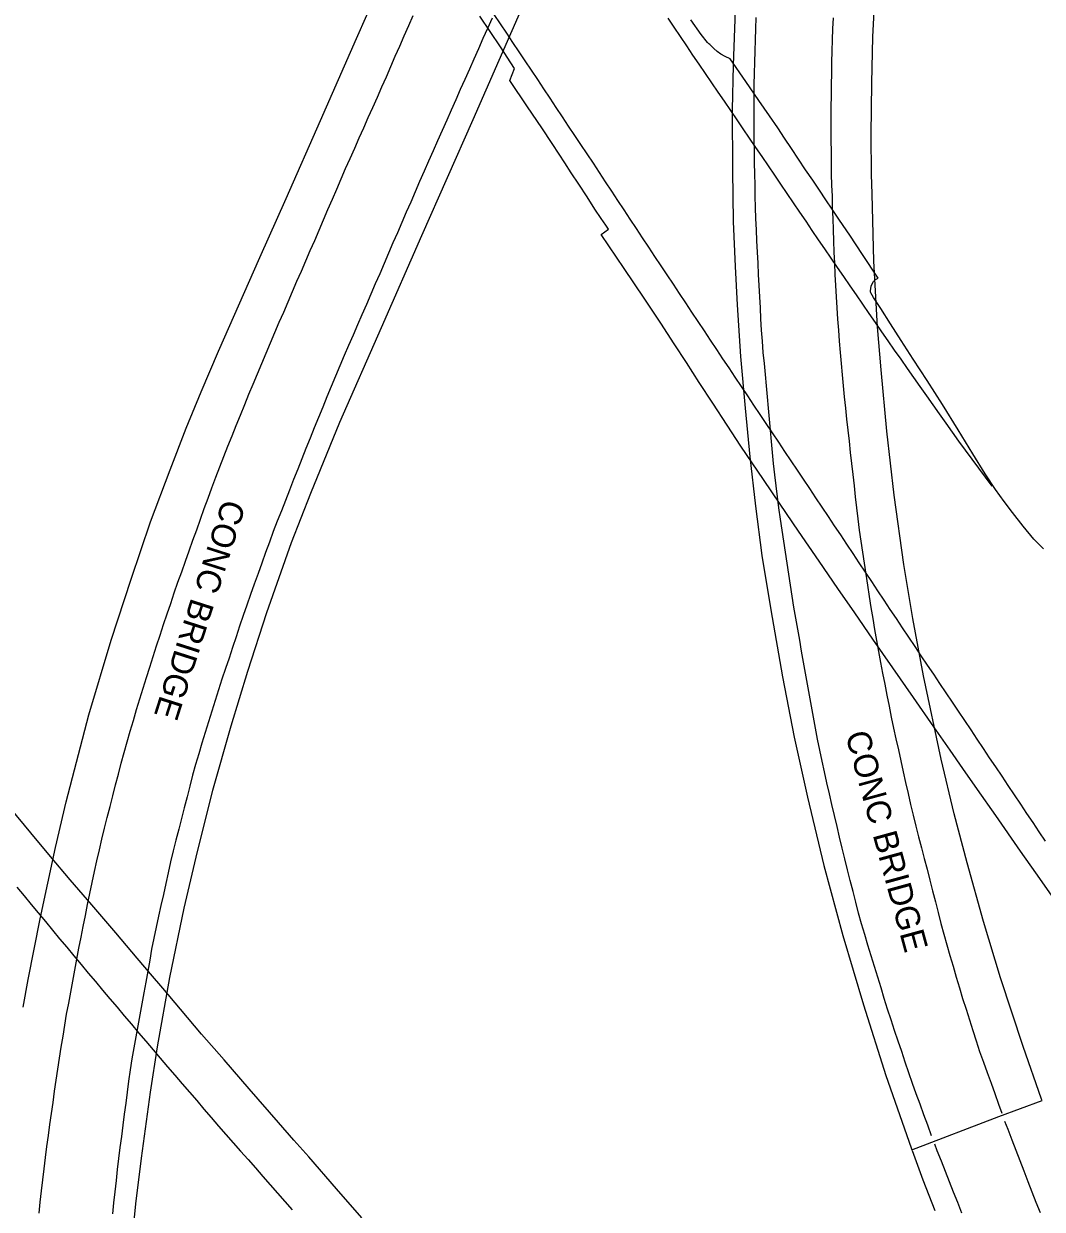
# Model space of a CAD drawing. Extents: x 1948091 to 1975253, y 787267 to 823306.
# Drawn here: x 1971410.9 to 1971639, y 795716.4 to 795981.8 of the extents above; entities that cross this region are included whole.
import ezdxf

# ---------------------------------------------------------------- set-up
doc = ezdxf.new("R2010")
doc.units = 0
for name, color, linetype in [('RD_EX_Bridge', 7, 'Continuous'), ('RD_EX_Pavement_Markings', 7, 'Continuous'), ('RD_EX_Road', 7, 'Continuous'), ('RD_TX_RoadID', 7, 'Continuous')]:
    doc.layers.add(name, color=color, linetype=linetype)

msp = doc.modelspace()

# ---------------------------------------------------------------- linework, layer by layer
at = {"layer": 'RD_EX_Bridge'}
for points in [[(1971560.98, 796072.58), (1971552.45, 796053.21), (1971542.05, 796029.77), (1971532.44, 796008.05), (1971523.1, 795986.87), (1971511.44, 795960.29), (1971499.96, 795934.32), (1971490.9, 795913.72), (1971481.56, 795892.55), (1971475.08, 795876.65), (1971470.79, 795865.58), (1971465.21, 795849.96), (1971460.96, 795836.83), (1971457.26, 795824.6), (1971453.16, 795810.17), (1971449.7, 795796.53), (1971446.71, 795783.84), (1971443.55, 795768.29), (1971440.77, 795752.77), (1971439.18, 795742.64), (1971437.16, 795727.87), (1971435.95, 795717.65), (1971434.59, 795704.07)], [(1971410.73, 795761.67), (1971411.87, 795767.88), (1971414.57, 795781.44), (1971418, 795797.42), (1971420.39, 795807.63), (1971425.46, 795827.09), (1971430.46, 795843.79), (1971434.92, 795857.44), (1971439.3, 795870.31), (1971443.65, 795881.96), (1971447.27, 795891.26), (1971450.6, 795899.38), (1971454.48, 795908.49), (1971463.72, 795929.48), (1971469.66, 795942.67), (1971477.37, 795960.17), (1971485.43, 795978.49), (1971496.94, 796004.69)], [(1971570.2, 795984.87), (1971569.71, 795972.52), (1971569.5, 795962.57), (1971569.57, 795948.97), (1971569.74, 795937.52), (1971570.18, 795927.44), (1971570.63, 795918.9), (1971571.4, 795907.32), (1971572.39, 795895.78), (1971573.44, 795884.85), (1971574.73, 795873.8), (1971576.19, 795862.75), (1971578.16, 795850.59), (1971580.75, 795835.6), (1971583.39, 795822.14), (1971586.4, 795808.69), (1971590.06, 795793.4), (1971594.3, 795777.72), (1971598.92, 795762.16), (1971603.9, 795746.37), (1971609.58, 795730.15), (1971609.73, 795729.75), (1971629.22, 795737.19), (1971638.9, 795740.75), (1971638.77, 795741.08), (1971634.69, 795752.85), (1971629.6, 795768.21), (1971625.79, 795780.83), (1971622.13, 795793.98), (1971619.19, 795804.95), (1971616.29, 795817.21), (1971612.39, 795835.81), (1971610, 795848.7), (1971607.97, 795860.79), (1971605.76, 795876.31), (1971604.11, 795890.62), (1971602.9, 795904.3), (1971602.03, 795913.98), (1971601.21, 795928.65), (1971601.09, 795934.71), (1971600.85, 795943.73), (1971600.73, 795948.04), (1971600.62, 795957.01), (1971600.76, 795968.52), (1971601.04, 795978.87), (1971601.51, 795988.89)]]:
    msp.add_lwpolyline(points, dxfattribs=at)
at = {"layer": 'RD_EX_Pavement_Markings'}
for points in [[(1971414.32, 795715.57), (1971414.57, 795718.05), (1971414.86, 795720.53), (1971415.16, 795723.02), (1971415.45, 795725.5), (1971415.75, 795727.98), (1971416.05, 795730.46), (1971416.4, 795732.93), (1971416.75, 795735.41), (1971417.1, 795737.88), (1971417.45, 795740.36), (1971417.8, 795742.83), (1971418.15, 795745.31), (1971418.52, 795747.78), (1971418.91, 795750.25), (1971419.3, 795752.72), (1971419.69, 795755.18), (1971420.07, 795757.65), (1971420.5, 795760.11), (1971420.95, 795762.57), (1971421.4, 795765.03), (1971421.85, 795767.49), (1971422.3, 795769.95), (1971422.75, 795772.4), (1971423.23, 795774.86), (1971423.72, 795777.31), (1971424.22, 795779.76), (1971424.71, 795782.21), (1971425.2, 795784.66), (1971425.69, 795787.11), (1971426.18, 795789.56), (1971426.71, 795792), (1971427.28, 795794.43), (1971427.84, 795796.87), (1971428.41, 795799.3), (1971428.98, 795801.73), (1971429.58, 795804.16), (1971430.21, 795806.58), (1971430.83, 795809), (1971431.45, 795811.42), (1971432.08, 795813.84), (1971432.7, 795816.26), (1971433.35, 795818.67), (1971434.05, 795821.07), (1971434.74, 795823.47), (1971435.44, 795825.87), (1971436.14, 795828.27), (1971436.87, 795830.66), (1971437.62, 795833.04), (1971438.36, 795835.43), (1971439.11, 795837.81), (1971439.85, 795840.2), (1971440.61, 795842.58), (1971441.41, 795844.95), (1971442.2, 795847.32), (1971443, 795849.69), (1971443.79, 795852.06), (1971444.59, 795854.42), (1971445.42, 795856.78), (1971446.26, 795859.13), (1971447.1, 795861.49), (1971447.94, 795863.84), (1971448.78, 795866.2), (1971449.62, 795868.55), (1971450.45, 795870.9), (1971451.29, 795873.26), (1971452.16, 795875.6), (1971453.04, 795877.94), (1971453.92, 795880.28), (1971454.81, 795882.62), (1971455.69, 795884.95), (1971456.61, 795887.28), (1971457.55, 795889.59), (1971458.49, 795891.91), (1971459.43, 795894.22), (1971460.37, 795896.54), (1971461.31, 795898.85), (1971462.27, 795901.16), (1971463.24, 795903.46), (1971464.21, 795905.77), (1971465.18, 795908.07), (1971466.15, 795910.37), (1971467.12, 795912.68), (1971468.09, 795914.98), (1971469.09, 795917.27), (1971470.08, 795919.56), (1971471.07, 795921.86), (1971472.07, 795924.15), (1971473.06, 795926.44), (1971474.05, 795928.73), (1971475.05, 795931.03), (1971476.04, 795933.32), (1971477.02, 795935.62), (1971478.01, 795937.91), (1971479, 795940.21), (1971479.99, 795942.5), (1971480.98, 795944.8), (1971481.97, 795947.09), (1971482.96, 795949.39), (1971483.98, 795951.67), (1971484.99, 795953.95), (1971486.01, 795956.24), (1971487.02, 795958.52), (1971488.04, 795960.8), (1971489.05, 795963.09), (1971490.07, 795965.37), (1971491.08, 795967.66), (1971492.08, 795969.94), (1971493.09, 795972.23), (1971494.09, 795974.52), (1971495.1, 795976.81), (1971496.1, 795979.1), (1971497.11, 795981.38), (1971498.11, 795983.67)], [(1971515.75, 795983.04), (1971514.73, 795980.75), (1971513.72, 795978.47), (1971512.7, 795976.18), (1971511.69, 795973.9), (1971510.67, 795971.62), (1971509.66, 795969.33), (1971508.64, 795967.05), (1971507.63, 795964.77), (1971506.61, 795962.48), (1971505.6, 795960.2), (1971504.59, 795957.92), (1971503.57, 795955.63), (1971502.56, 795953.35), (1971501.54, 795951.07), (1971500.54, 795948.78), (1971499.54, 795946.49), (1971498.54, 795944.2), (1971497.55, 795941.9), (1971496.55, 795939.61), (1971495.56, 795937.32), (1971494.56, 795935.03), (1971493.57, 795932.74), (1971492.57, 795930.44), (1971491.58, 795928.15), (1971490.59, 795925.86), (1971489.6, 795923.56), (1971488.6, 795921.27), (1971487.61, 795918.98), (1971486.62, 795916.68), (1971485.62, 795914.39), (1971484.63, 795912.1), (1971483.64, 795909.81), (1971482.64, 795907.51), (1971481.65, 795905.22), (1971480.66, 795902.93), (1971479.71, 795900.62), (1971478.77, 795898.3), (1971477.83, 795895.99), (1971476.89, 795893.67), (1971475.95, 795891.36), (1971475.01, 795889.04), (1971474.07, 795886.73), (1971473.15, 795884.4), (1971472.23, 795882.08), (1971471.32, 795879.75), (1971470.41, 795877.43), (1971469.5, 795875.1), (1971468.58, 795872.77), (1971467.67, 795870.45), (1971466.77, 795868.12), (1971465.9, 795865.78), (1971465.05, 795863.42), (1971464.2, 795861.07), (1971463.36, 795858.72), (1971462.51, 795856.37), (1971461.66, 795854.02), (1971460.82, 795851.67), (1971460.01, 795849.31), (1971459.22, 795846.94), (1971458.43, 795844.57), (1971457.64, 795842.2), (1971456.85, 795839.82), (1971456.06, 795837.45), (1971455.27, 795835.08), (1971454.49, 795832.71), (1971453.73, 795830.33), (1971453, 795827.94), (1971452.26, 795825.55), (1971451.53, 795823.17), (1971450.79, 795820.78), (1971450.06, 795818.39), (1971449.35, 795815.99), (1971448.71, 795813.58), (1971448.09, 795811.16), (1971447.46, 795808.74), (1971446.84, 795806.32), (1971446.21, 795803.9), (1971445.59, 795801.48), (1971444.96, 795799.06), (1971444.34, 795796.64), (1971443.76, 795794.21), (1971443.22, 795791.77), (1971442.68, 795789.33), (1971442.15, 795786.89), (1971441.61, 795784.45), (1971441.07, 795782.01), (1971440.54, 795779.57), (1971440, 795777.13), (1971439.53, 795774.67), (1971439.09, 795772.22), (1971438.65, 795769.76), (1971438.2, 795767.3), (1971437.76, 795764.84), (1971437.32, 795762.38), (1971436.88, 795759.92), (1971436.44, 795757.46), (1971436, 795755), (1971435.56, 795752.54), (1971435.11, 795750.08), (1971434.71, 795747.61), (1971434.37, 795745.14), (1971434.04, 795742.66), (1971433.72, 795740.18), (1971433.39, 795737.71), (1971433.07, 795735.23), (1971432.75, 795732.75), (1971432.42, 795730.27), (1971432.1, 795727.8), (1971431.82, 795725.31), (1971431.55, 795722.83), (1971431.29, 795720.34), (1971431.02, 795717.86), (1971430.75, 795715.38)], [(1971516.17, 795983.86), (1971517.56, 795981.78), (1971518.95, 795979.71), (1971520.34, 795977.63), (1971521.73, 795975.55), (1971523.11, 795973.47), (1971524.5, 795971.39), (1971525.89, 795969.31), (1971527.27, 795967.23), (1971528.66, 795965.15), (1971530.05, 795963.07), (1971531.43, 795960.99), (1971532.82, 795958.9), (1971534.2, 795956.82), (1971535.59, 795954.74), (1971536.98, 795952.66), (1971538.36, 795950.58), (1971539.73, 795948.49), (1971541.11, 795946.41), (1971542.49, 795944.32), (1971543.87, 795942.24), (1971545.25, 795940.15), (1971546.63, 795938.07), (1971548.01, 795935.98), (1971549.38, 795933.9), (1971550.76, 795931.81), (1971552.14, 795929.73), (1971553.53, 795927.65), (1971554.91, 795925.57), (1971556.29, 795923.48), (1971557.67, 795921.4), (1971559.06, 795919.32), (1971560.44, 795917.24), (1971561.82, 795915.16), (1971563.21, 795913.08), (1971564.59, 795910.99), (1971565.97, 795908.91), (1971567.35, 795906.83), (1971568.74, 795904.75), (1971570.12, 795902.67), (1971571.52, 795900.59), (1971572.91, 795898.52), (1971574.3, 795896.44), (1971575.69, 795894.36), (1971577.08, 795892.29), (1971578.47, 795890.21), (1971579.86, 795888.13), (1971581.25, 795886.06), (1971582.64, 795883.98), (1971584.03, 795881.9), (1971585.42, 795879.83), (1971586.81, 795877.75), (1971588.2, 795875.68), (1971589.59, 795873.6), (1971590.98, 795871.52), (1971592.37, 795869.45), (1971593.76, 795867.37), (1971595.14, 795865.29), (1971596.52, 795863.2), (1971597.91, 795861.12), (1971599.29, 795859.04), (1971600.68, 795856.96), (1971602.06, 795854.88), (1971603.45, 795852.8), (1971604.83, 795850.72), (1971606.22, 795848.64), (1971607.61, 795846.56), (1971609, 795844.49), (1971610.39, 795842.41), (1971611.79, 795840.34), (1971613.18, 795838.26), (1971614.57, 795836.19), (1971615.96, 795834.11), (1971617.35, 795832.04), (1971618.74, 795829.96), (1971620.14, 795827.89), (1971621.53, 795825.81), (1971622.92, 795823.74), (1971624.31, 795821.66), (1971625.7, 795819.59), (1971627.09, 795817.51), (1971628.48, 795815.44), (1971629.88, 795813.36), (1971631.27, 795811.29), (1971632.65, 795809.21), (1971634.04, 795807.13), (1971635.43, 795805.05), (1971636.82, 795802.97), (1971638.21, 795800.9), (1971639.6, 795798.82)], [(1971627.71, 795878.29), (1971626.23, 795880.3), (1971624.74, 795882.32), (1971623.26, 795884.33), (1971621.78, 795886.34), (1971620.3, 795888.35), (1971618.85, 795890.38), (1971617.41, 795892.42), (1971615.97, 795894.46), (1971614.53, 795896.5), (1971613.08, 795898.54), (1971611.64, 795900.58), (1971610.2, 795902.62), (1971608.76, 795904.66), (1971607.32, 795906.7), (1971605.89, 795908.75), (1971604.47, 795910.81), (1971603.05, 795912.86), (1971601.63, 795914.92), (1971600.2, 795916.98), (1971598.78, 795919.03), (1971597.36, 795921.09), (1971595.94, 795923.15), (1971594.53, 795925.21), (1971593.11, 795927.27), (1971591.7, 795929.33), (1971590.28, 795931.39), (1971588.87, 795933.45), (1971587.46, 795935.51), (1971586.05, 795937.58), (1971584.65, 795939.65), (1971583.25, 795941.72), (1971581.84, 795943.79), (1971580.44, 795945.86), (1971579.04, 795947.93), (1971577.63, 795950), (1971576.23, 795952.06), (1971574.83, 795954.13), (1971573.42, 795956.2), (1971572.01, 795958.26), (1971570.6, 795960.33), (1971569.19, 795962.39), (1971567.78, 795964.46), (1971566.37, 795966.52), (1971564.97, 795968.59), (1971563.56, 795970.65), (1971562.15, 795972.72), (1971560.74, 795974.78), (1971559.34, 795976.85), (1971557.95, 795978.93), (1971556.56, 795981.01), (1971555.16, 795983.09)], [(1971614.18, 795732.88), (1971613.32, 795735.22), (1971612.46, 795737.57), (1971611.6, 795739.92), (1971610.74, 795742.26), (1971609.88, 795744.61), (1971609.05, 795746.97), (1971608.26, 795749.34), (1971607.47, 795751.71), (1971606.68, 795754.08), (1971605.89, 795756.45), (1971605.1, 795758.82), (1971604.31, 795761.19), (1971603.57, 795763.58), (1971602.84, 795765.97), (1971602.11, 795768.36), (1971601.38, 795770.75), (1971600.65, 795773.14), (1971599.92, 795775.53), (1971599.19, 795777.92), (1971598.46, 795780.31), (1971597.78, 795782.72), (1971597.18, 795785.14), (1971596.57, 795787.57), (1971595.96, 795789.99), (1971595.35, 795792.42), (1971594.74, 795794.84), (1971594.14, 795797.27), (1971593.56, 795799.7), (1971593, 795802.13), (1971592.43, 795804.57), (1971591.86, 795807), (1971591.3, 795809.44), (1971590.73, 795811.87), (1971590.21, 795814.32), (1971589.69, 795816.76), (1971589.17, 795819.21), (1971588.65, 795821.65), (1971588.16, 795824.1), (1971587.71, 795826.56), (1971587.26, 795829.02), (1971586.82, 795831.48), (1971586.37, 795833.94), (1971585.94, 795836.4), (1971585.5, 795838.86), (1971585.07, 795841.33), (1971584.63, 795843.79), (1971584.2, 795846.25), (1971583.77, 795848.71), (1971583.33, 795851.17), (1971582.92, 795853.64), (1971582.55, 795856.11), (1971582.17, 795858.58), (1971581.8, 795861.05), (1971581.43, 795863.52), (1971581.05, 795866), (1971580.68, 795868.47), (1971580.3, 795870.94), (1971579.99, 795873.42), (1971579.69, 795875.9), (1971579.39, 795878.38), (1971579.09, 795880.86), (1971578.78, 795883.35), (1971578.52, 795885.83), (1971578.29, 795888.32), (1971578.07, 795890.81), (1971577.84, 795893.3), (1971577.62, 795895.79), (1971577.39, 795898.28), (1971577.17, 795900.77), (1971576.94, 795903.26), (1971576.72, 795905.75), (1971576.49, 795908.24), (1971576.27, 795910.73), (1971576.08, 795913.22), (1971575.95, 795915.72), (1971575.82, 795918.21), (1971575.68, 795920.71), (1971575.55, 795923.21), (1971575.42, 795925.7), (1971575.3, 795928.2), (1971575.18, 795930.7), (1971575.05, 795933.19), (1971574.93, 795935.69), (1971574.8, 795938.19), (1971574.73, 795940.69), (1971574.68, 795943.18), (1971574.63, 795945.68), (1971574.58, 795948.18), (1971574.53, 795950.68), (1971574.48, 795953.18), (1971574.43, 795955.68), (1971574.42, 795958.18), (1971574.43, 795960.68), (1971574.43, 795963.18), (1971574.43, 795965.68), (1971574.47, 795968.18), (1971574.53, 795970.68), (1971574.6, 795973.18), (1971574.66, 795975.68), (1971574.72, 795978.18), (1971574.78, 795980.68), (1971574.87, 795983.17)], [(1971592.1, 795983.16), (1971592.01, 795980.66), (1971591.92, 795978.17), (1971591.84, 795975.67), (1971591.76, 795973.17), (1971591.73, 795970.67), (1971591.69, 795968.17), (1971591.65, 795965.67), (1971591.61, 795963.17), (1971591.6, 795960.67), (1971591.62, 795958.17), (1971591.63, 795955.67), (1971591.65, 795953.17), (1971591.66, 795950.67), (1971591.71, 795948.17), (1971591.79, 795945.67), (1971591.87, 795943.18), (1971591.94, 795940.68), (1971592.02, 795938.18), (1971592.1, 795935.68), (1971592.18, 795933.18), (1971592.25, 795930.68), (1971592.39, 795928.19), (1971592.53, 795925.69), (1971592.67, 795923.2), (1971592.81, 795920.7), (1971592.96, 795918.2), (1971593.1, 795915.71), (1971593.29, 795913.22), (1971593.49, 795910.72), (1971593.7, 795908.23), (1971593.91, 795905.74), (1971594.12, 795903.25), (1971594.34, 795900.76), (1971594.61, 795898.28), (1971594.88, 795895.79), (1971595.15, 795893.31), (1971595.42, 795890.82), (1971595.7, 795888.34), (1971595.97, 795885.85), (1971596.24, 795883.37), (1971596.53, 795880.88), (1971596.81, 795878.4), (1971597.09, 795875.91), (1971597.38, 795873.43), (1971597.66, 795870.95), (1971597.96, 795868.47), (1971598.33, 795865.99), (1971598.7, 795863.52), (1971599.06, 795861.05), (1971599.43, 795858.58), (1971599.8, 795856.1), (1971600.17, 795853.63), (1971600.57, 795851.16), (1971601, 795848.7), (1971601.42, 795846.24), (1971601.85, 795843.77), (1971602.28, 795841.31), (1971602.71, 795838.85), (1971603.19, 795836.4), (1971603.67, 795833.94), (1971604.16, 795831.49), (1971604.64, 795829.04), (1971605.12, 795826.59), (1971605.66, 795824.14), (1971606.19, 795821.7), (1971606.72, 795819.26), (1971607.25, 795816.82), (1971607.79, 795814.38), (1971608.32, 795811.93), (1971608.89, 795809.5), (1971609.47, 795807.07), (1971610.05, 795804.64), (1971610.63, 795802.2), (1971611.24, 795799.78), (1971611.87, 795797.36), (1971612.5, 795794.95), (1971613.14, 795792.53), (1971613.77, 795790.11), (1971614.4, 795787.69), (1971615.02, 795785.27), (1971615.64, 795782.85), (1971616.26, 795780.43), (1971616.88, 795778.01), (1971617.55, 795775.6), (1971618.26, 795773.2), (1971618.97, 795770.81), (1971619.69, 795768.41), (1971620.4, 795766.01), (1971621.12, 795763.62), (1971621.88, 795761.24), (1971622.64, 795758.86), (1971623.41, 795756.48), (1971624.17, 795754.1), (1971624.93, 795751.72), (1971625.76, 795749.36), (1971626.62, 795747.01), (1971627.47, 795744.67), (1971628.32, 795742.32), (1971629.18, 795739.97), (1971629.92, 795737.93)], [(1971409.36, 795788.53), (1971410.95, 795786.61), (1971412.55, 795784.68), (1971414.14, 795782.76), (1971415.74, 795780.84), (1971417.34, 795778.91), (1971418.93, 795776.99), (1971420.53, 795775.07), (1971422.13, 795773.14), (1971423.72, 795771.22), (1971425.33, 795769.3), (1971426.94, 795767.39), (1971428.55, 795765.48), (1971430.16, 795763.57), (1971431.78, 795761.66), (1971433.39, 795759.76), (1971435, 795757.85), (1971436.62, 795755.94), (1971438.23, 795754.03), (1971439.84, 795752.12), (1971441.47, 795750.22), (1971443.1, 795748.32), (1971444.73, 795746.43), (1971446.36, 795744.53), (1971447.99, 795742.64), (1971449.62, 795740.74), (1971451.25, 795738.85), (1971452.88, 795736.95), (1971454.51, 795735.06), (1971456.16, 795733.18), (1971457.81, 795731.3), (1971459.46, 795729.43), (1971461.11, 795727.55), (1971462.76, 795725.67), (1971464.41, 795723.79), (1971466.06, 795721.92), (1971467.71, 795720.04), (1971469.36, 795718.16), (1971471.01, 795716.28)], [(1971638.54, 795715.62), (1971637.6, 795717.94), (1971636.65, 795720.25), (1971635.76, 795722.59), (1971634.87, 795724.92), (1971633.98, 795727.26), (1971633.09, 795729.59), (1971632.2, 795731.92), (1971631.31, 795734.26), (1971630.6, 795736.11)], [(1971620.93, 795715.59), (1971620.01, 795717.91), (1971619.08, 795720.23), (1971618.16, 795722.55), (1971617.25, 795724.88), (1971616.35, 795727.21), (1971615.45, 795729.54), (1971614.88, 795731)]]:
    msp.add_lwpolyline(points, dxfattribs=at)
at = {"layer": 'RD_EX_Road'}
for points in [[(1971640.98, 795786.76), (1971637.5, 795791.75), (1971634.11, 795796.61), (1971628.54, 795804.58), (1971624.48, 795810.39), (1971621.19, 795815.09), (1971618.32, 795819.16), (1971614.64, 795824.42), (1971610.08, 795830.98), (1971605.47, 795837.62), (1971601.02, 795844.08), (1971596.96, 795849.97), (1971593.21, 795855.4), (1971589, 795861.5), (1971584.38, 795868.24), (1971580.25, 795874.26), (1971576.5, 795879.75), (1971571.48, 795887.27), (1971568.4, 795891.96), (1971565.2, 795896.84), (1971562.16, 795901.5), (1971559.27, 795905.95), (1971556.54, 795910.17), (1971553.52, 795914.79), (1971549.79, 795920.41), (1971545.34, 795927.03), (1971540.17, 795934.65), (1971541.81, 795935.81), (1971541.2, 795936.71), (1971540.19, 795938.21), (1971538.8, 795940.33), (1971537.03, 795943.04), (1971535.16, 795945.91), (1971533.49, 795948.46), (1971532.03, 795950.7), (1971530.77, 795952.63), (1971529.21, 795954.99), (1971526.86, 795958.53), (1971523.7, 795963.23), (1971519.73, 795969.11), (1971520.8, 795971.76), (1971517.61, 795976.6), (1971513.01, 795983.53)], [(1971639.23, 795864.25), (1971637.08, 795866.46), (1971634.65, 795869.37), (1971632.31, 795872.37), (1971630.41, 795874.85), (1971628.51, 795877.51), (1971626.18, 795881.07), (1971623.38, 795885.53), (1971620.08, 795890.91), (1971616.58, 795896.58), (1971613.19, 795901.91), (1971610.06, 795906.74), (1971607.36, 795910.91), (1971604.96, 795914.6), (1971602.78, 795918.03), (1971601.19, 795920.56), (1971600.56, 795921.56), (1971600.51, 795921.74), (1971600.51, 795922.05), (1971600.66, 795923.03), (1971600.84, 795923.61), (1971601.16, 795924.11), (1971601.62, 795924.53), (1971602.2, 795924.87), (1971598.72, 795930.13), (1971595.85, 795934.46), (1971593.58, 795937.86), (1971591.91, 795940.33), (1971590.52, 795942.39), (1971589.06, 795944.54), (1971587.55, 795946.79), (1971585.97, 795949.13), (1971584.38, 795951.5), (1971582.8, 795953.85), (1971581.24, 795956.18), (1971579.71, 795958.47), (1971577.89, 795961.16), (1971575.52, 795964.64), (1971572.58, 795968.91), (1971569.07, 795973.98), (1971567.92, 795974.47), (1971566.99, 795974.97), (1971566.19, 795975.56), (1971565.41, 795976.3), (1971564.74, 795976.95), (1971564.48, 795977.16), (1971564.27, 795977.29), (1971563.96, 795977.59), (1971562.56, 795979.42), (1971560.27, 795982.66)], [(1971486.58, 795714.53), (1971480.93, 795720.99), (1971474.71, 795728.13), (1971471.38, 795731.92), (1971467.92, 795735.87), (1971461.35, 795743.38), (1971455.73, 795749.85), (1971450.72, 795755.66), (1971445.98, 795761.22), (1971442, 795765.91), (1971439.26, 795769.14), (1971436.26, 795772.67), (1971431.48, 795778.27), (1971426.1, 795784.57), (1971421.32, 795790.16), (1971416.86, 795795.42), (1971412.46, 795800.69), (1971407.84, 795806.29)], [(1971609.79, 795729.58), (1971612.23, 795722.98), (1971614.88, 795716.13)]]:
    msp.add_lwpolyline(points, dxfattribs=at)

# ---------------------------------------------------------------- texts
at = {"layer": 'RD_TX_RoadID'}
for rotation, p in [(252.2772, (1971455.52, 795875.64)), (285.2708, (1971594.82, 795822.73))]:
    msp.add_text('CONC BRIDGE', height=5.4, rotation=rotation, dxfattribs=at).set_placement(p)

doc.saveas('drawing.dxf')
